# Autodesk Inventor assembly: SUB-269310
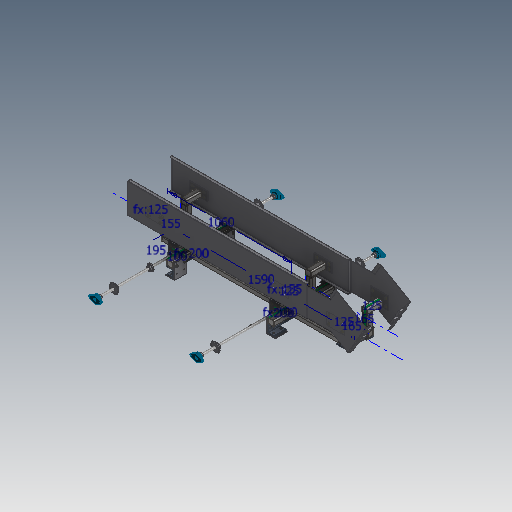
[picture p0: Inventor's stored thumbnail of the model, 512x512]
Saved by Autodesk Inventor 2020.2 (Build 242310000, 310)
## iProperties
Created: 2000-02
Part Number: SUB-269310
Document SubType Name: Assembly
Designer: sspink
Mass: 65770.7 g
Surface Area: 56911.4 cm^2
Volume: 11460 cm^3
Density: 5.73915 g/cm^3
Control State: 0
Checked Out: False
Master: False
Shininess: 0.0
Length Units: 11269
Angle Units: 11279
Time Units: 11290
Mass Units: 11283
Length Display Precision: 3
Angle Display Precision: 2
Compacted: True
Dimensions: 570,1x1560x2033,5 mm
Mass: 65,771 kg
DocNumber: SUB-269310.iam
Folder: 01 - Themengebiete\Simplification\01 - Packaging machine\
VDS_Category: 3D Komponenten
Density: 0.0
Volumn: 0.0
Area: 0.0
PropertySet Name: Model Information
Author: sspink
Revision Number: -
Title: SUB-269310
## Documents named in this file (26)
- D:\07 - DEMODATEN\OTX 2019 - Dataset - UPDATE - Dez2019\Designs\07-Packing machine\SUB-269310.iam
- D:\07 - DEMODATEN\OTX 2019 - Dataset - UPDATE - Dez2019\Designs\07-Packing machine\500666L.iam
- D:\07 - DEMODATEN\OTX 2019 - Dataset - UPDATE - Dez2019\Designs\07-Packing machine\Parts\ADSK-011632.ipt
- D:\07 - DEMODATEN\OTX 2019 - Dataset - UPDATE - Dez2019\Designs\07-Packing machine\Parts\ADSK-011655.ipt
- D:\07 - DEMODATEN\OTX 2019 - Dataset - UPDATE - Dez2019\Designs\07-Packing machine\500665L.iam
- D:\07 - DEMODATEN\OTX 2019 - Dataset - UPDATE - Dez2019\Designs\07-Packing machine\Parts\ADSK-011625.ipt
- D:\07 - DEMODATEN\OTX 2019 - Dataset - UPDATE - Dez2019\Designs\07-Packing machine\Parts\ADSK-011656.ipt
- D:\07 - DEMODATEN\OTX 2019 - Dataset - UPDATE - Dez2019\Designs\07-Packing machine\Parts\ADSK-011657.ipt
- D:\07 - DEMODATEN\OTX 2019 - Dataset - UPDATE - Dez2019\Designs\07-Packing machine\Parts\ADSK-011333.ipt
- D:\07 - DEMODATEN\OTX 2019 - Dataset - UPDATE - Dez2019\Designs\07-Packing machine\Parts\ADSK-011663.ipt
- D:\07 - DEMODATEN\OTX 2019 - Dataset - UPDATE - Dez2019\Designs\07-Packing machine\Parts\ADSK-011714.ipt
- D:\07 - DEMODATEN\OTX 2019 - Dataset - UPDATE - Dez2019\Designs\07-Packing machine\Parts\ADSK-011716.ipt
- D:\07 - DEMODATEN\OTX 2019 - Dataset - UPDATE - Dez2019\Designs\07-Packing machine\Parts\ADSK-011741.ipt
- D:\07 - DEMODATEN\OTX 2019 - Dataset - UPDATE - Dez2019\Designs\07-Packing machine\Parts\ADSK-011723.ipt
- D:\07 - DEMODATEN\OTX 2019 - Dataset - UPDATE - Dez2019\Designs\07-Packing machine\Parts\ADSK-011664.ipt
- D:\07 - DEMODATEN\OTX 2019 - Dataset - UPDATE - Dez2019\Designs\07-Packing machine\500665R.iam
- D:\07 - DEMODATEN\OTX 2019 - Dataset - UPDATE - Dez2019\Designs\07-Packing machine\Parts\ADSK-011626.ipt
- D:\07 - DEMODATEN\OTX 2019 - Dataset - UPDATE - Dez2019\Content Center Files\de-DE\ISO 2491 - A\ISO 2491 - A  5 x 3 x 32.ipt
- D:\07 - DEMODATEN\OTX 2019 - Dataset - UPDATE - Dez2019\Content Center Files\de-DE\ISO 4026\ISO 4026 - M5 x 8 - ISO.ipt
- D:\07 - DEMODATEN\OTX 2019 - Dataset - UPDATE - Dez2019\Content Center Files\de-DE\DIN 125-1  B\DIN 125-1 - B 8,4.ipt
- D:\07 - DEMODATEN\OTX 2019 - Dataset - UPDATE - Dez2019\Content Center Files\de-DE\ISO 4762(2)\ISO 4762 - M8 x 16ISO.ipt
- D:\07 - DEMODATEN\OTX 2019 - Dataset - UPDATE - Dez2019\Content Center Files\de-DE\ISO 4762(2)\ISO 4762 - M8 x 20ISO.ipt
- D:\07 - DEMODATEN\OTX 2019 - Dataset - UPDATE - Dez2019\Content Center Files\de-DE\ISO 10642(1)\ISO 10642 - M8x16.ipt
- D:\07 - DEMODATEN\OTX 2019 - Dataset - UPDATE - Dez2019\Content Center Files\de-DE\DIN 125-1  B\DIN 125-1 - B 5,3.ipt
- D:\07 - DEMODATEN\OTX 2019 - Dataset - UPDATE - Dez2019\Content Center Files\de-DE\ISO 4762(2)\ISO 4762 - M5 x 12ISO.ipt
- D:\07 - DEMODATEN\OTX 2019 - Dataset - UPDATE - Dez2019\Content Center Files\de-DE\ISO 4032(1)\ISO 4032 - M8DIN EN.ipt
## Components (274 placed, 25 different names)
1. 500666L:2 [sub-assembly] — Fluchtend:34, Fluchtend:35, Fluchtend:36, Passend:51, Passend:52, Passend:53, Passend:54, Fluchtend:37, Passend:58, Passend:59, Passend:64, Fluchtend:38, Fluchtend:41, Passend:143, Passend:81, Passend:82, Fluchtend:46, Passend:115, Passend:116, Passend:117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
2. ADSK-011632:3 — Passend:45, Passend:46, Passend:47
3. ADSK-011655:1 — Fluchtend:34, Passend:45, Passend:46, Passend:47, Passend:48, Passend:49, Passend:50, Passend:122, Fluchtend:55, Passend:414, Passend:416
4. ADSK-011655:2 — Fluchtend:35, Fluchtend:36, Passend:56, Passend:57, Passend:60, Passend:61, Passend:62, Passend:63, Passend:121, Passend:426, Passend:428
5. 500665L:1 [sub-assembly] — Passend:112, Passend:113, Passend:114, Passend:229, Passend:230, Fluchtend:77, Passend:257, Passend:259, Passend:326, Passend:328, Passend:330, Passend:332
6. ADSK-011625:1 — Passend:75, Passend:76, Passend:77, Passend:78, Passend:112, Passend:113, Passend:114, Passend:155, Passend:156
7. ADSK-011656:1 — Passend:115, Passend:116, Passend:117
8. ADSK-011657:1 — Passend:82, Passend:83, Fluchtend:47, Passend:84, Passend:85, Passend:90, Passend:92, Passend:98, Fluchtend:62, Fluchtend:66
9. ADSK-011657:2 — Passend:81, Fluchtend:46, Fluchtend:47, Passend:86, Passend:87, Passend:88, Passend:89, Passend:91, Passend:97, Fluchtend:61, Fluchtend:65, Passend:239, Passend:241, Passend:243, Passend:245
10. ADSK-011333:1 — Passend:86, Passend:87, Passend:88, Passend:263, Passend:265
11. ADSK-011333:2 — Passend:83, Passend:84, Passend:85, Passend:275, Passend:277
12. ADSK-011663:1 — Mate:34, Passend:93, Fluchtend:50, Passend:96, Passend:102, Passend:101, Passend:108, Passend:168, Passend:169, Passend:170, Passend:171, Passend:172, Passend:173, Fluchtend:67, Passend:174, Passend:226
13. ADSK-011663:2 — Passend:32, Mate:35, Passend:94, Fluchtend:51, Passend:95, Passend:103, Passend:177, Passend:178, Passend:179, Passend:180
14. ADSK-011714:1 — Passend:90, Passend:92, Passend:94, Fluchtend:51, Passend:100, Passend:167, Passend:182
15. ADSK-011714:2 — Passend:96, Passend:97, Passend:99, Passend:105
16. ADSK-011714:3 — Passend:95, Passend:98, Passend:100, Passend:104
17. ADSK-011714:4 — Passend:89, Passend:91, Passend:93, Fluchtend:50, Passend:99, Passend:106, Fluchtend:52, Passend:181
18. ADSK-011716:1 — Passend:102, Passend:105
19. ADSK-011716:2 — Passend:103, Passend:104
20. ADSK-011716:3 — Passend:32, Passend:167
21. ADSK-011716:4 — Passend:101, Passend:106
22. ADSK-011723:2 — Passend:108, Fluchtend:52, Passend:111, Fluchtend:67, Passend:175
23. ADSK-011741:1 — Mate:35, Fluchtend:53, Passend:180, Drehung:1
24. ADSK-011741:2 — Mate:34, Passend:111, Fluchtend:53, Passend:174, Drehung:1
25. ADSK-011664:1 — Passend:75, Passend:76, Passend:155
26. ADSK-011664:2 — Passend:77, Passend:78, Passend:156
27. ADSK-011632:6 — Passend:48, Passend:49, Passend:50
28. ADSK-011632:7 — Passend:51, Passend:53, Passend:55, Fluchtend:37
29. ADSK-011632:8 — Passend:52, Passend:54, Passend:55
30. ADSK-011632:9 — Passend:59, Passend:64, Fluchtend:38, Fluchtend:39, Passend:65
31. ADSK-011632:10 — Passend:58, Fluchtend:39, Passend:65
32. ADSK-011632:11 — Passend:57, Passend:60, Passend:61
33. ADSK-011632:12 — Passend:56, Passend:62, Passend:63
34. ADSK-011632:13 — Fluchtend:41, Passend:143, Passend:142
35. ADSK-011632:14
36. ADSK-011632:18 — Passend:227, Passend:279, Passend:280
37. ADSK-011632:19 — Passend:228, Passend:278, Fluchtend:80, Passend:280
38. ADSK-011632:20 — Passend:232, Passend:233, Passend:235, Fluchtend:78
39. ADSK-011632:21 — Passend:231, Passend:234, Passend:235
40. ADSK-011632:22 — Passend:236, Fluchtend:79, Passend:237
41. ADSK-011632:15
42. ADSK-011632:16
43. ADSK-011632:17
44. ADSK-011655:3 — Passend:135, Fluchtend:56, Fluchtend:57, Passend:418, Passend:420
45. ADSK-011655:4 — Passend:136, Fluchtend:58, Fluchtend:59, Passend:422, Passend:424
46. ADSK-011656:2 — Passend:137, Passend:147, Passend:148
47. 500665R:1 [sub-assembly] — Passend:140, Fluchtend:60, Passend:141, Passend:144, Passend:145, Passend:146, Passend:255, Passend:261, Passend:318, Passend:320, Passend:322, Passend:324
48. ADSK-011626:1 — Passend:144, Passend:145, Passend:146, Passend:149, Passend:150, Passend:151, Passend:152, Passend:153, Passend:154
49. ADSK-011664:3 — Passend:149, Passend:152, Passend:153
50. ADSK-011664:4 — Passend:150, Passend:151, Passend:154
51. ADSK-011657:3 — Fluchtend:64, Passend:163, Fluchtend:66, Passend:164, Passend:165, Passend:166, Passend:224, Fluchtend:76, Passend:225
52. ADSK-011657:4 — Passend:157, Fluchtend:63, Fluchtend:65, Passend:160, Passend:161, Passend:162, Passend:202, Passend:203, Passend:204, Passend:247, Passend:249, Passend:251, Passend:253
53. ADSK-011333:3 — Passend:164, Passend:165, Passend:166, Passend:271, Passend:273
54. ADSK-011333:4 — Passend:160, Passend:161, Passend:162, Passend:267, Passend:269
55. ADSK-011663:3 — Passend:187, Passend:188, Passend:202, Passend:226
56. ADSK-011714:5 — Passend:204
57. ADSK-011714:6 — Passend:203, Fluchtend:71
58. ADSK-011716:5 — Passend:188
59. ADSK-011716:6 — Passend:187
60. ADSK-011723:3
61. ADSK-011741:3 — Drehung:2
62. ADSK-011663:4 — Passend:209, Passend:210, Passend:224
63. ADSK-011714:7 — Passend:225
64. ADSK-011714:8 — Fluchtend:75, Fluchtend:76
65. ADSK-011716:7 — Passend:210
66. ADSK-011716:8 — Passend:209
67. ADSK-011723:4
68. ADSK-011741:4 — Drehung:2
69. DIN 125-1 B B 8,4:13
70. DIN 125-1 B B 8,4:14 — Passend:398, Passend:400, Passend:402, Passend:404
71. DIN 125-1 B B 8,4:15
72. DIN 125-1 B B 8,4:16
73. DIN 125-1 B B 8,4:17 — Passend:318
74. DIN 125-1 B B 8,4:18 — Passend:320
75. DIN 125-1 B B 8,4:19 — Passend:322
76. DIN 125-1 B B 8,4:20 — Passend:324
77. DIN 125-1 B B 8,4:21 — Passend:326
78. DIN 125-1 B B 8,4:22 — Passend:328
79. DIN 125-1 B B 8,4:23 — Passend:330
80. DIN 125-1 B B 8,4:24 — Passend:332
81. DIN 125-1 B B 8,4:25 — Passend:406, Passend:408, Passend:410, Passend:412
82. DIN 125-1 B B 8,4:26
83. DIN 125-1 B B 8,4:27
84. DIN 125-1 B B 8,4:28
85. DIN EN 24032 M8:1
86. DIN EN 24032 M8:2
87. DIN EN 24032 M8:3
88. DIN EN 24032 M8:4
89. DIN EN 24032 M8:5
90. DIN EN 24032 M8:6
91. DIN EN 24032 M8:7
92. DIN EN 24032 M8:8
93. DIN 125-1 B B 8,4:29 — Passend:334
94. DIN 125-1 B B 8,4:30 — Passend:336
95. DIN 125-1 B B 8,4:31 — Passend:338
96. DIN 125-1 B B 8,4:32 — Passend:340
97. DIN 125-1 B B 8,4:33 — Passend:342
98. DIN 125-1 B B 8,4:34 — Passend:344
99. DIN 125-1 B B 8,4:35 — Passend:346
100. DIN 125-1 B B 8,4:36 — Passend:348
101. DIN 125-1 B B 8,4:37 — Passend:382, Passend:384, Passend:386, Passend:388, Passend:390, Passend:392, Passend:394, Passend:396
102. DIN 125-1 B B 8,4:38
103. DIN 125-1 B B 8,4:39
104. DIN 125-1 B B 8,4:40
105. DIN 125-1 B B 8,4:41
106. DIN 125-1 B B 8,4:42
107. DIN 125-1 B B 8,4:43
108. DIN 125-1 B B 8,4:44
109. DIN 125-1 B B 8,4:45
110. DIN 125-1 B B 8,4:46
111. DIN 125-1 B B 8,4:47
112. DIN 125-1 B B 8,4:48 — Passend:366, Passend:368, Passend:370, Passend:372, Passend:374, Passend:376, Passend:378, Passend:380
113. DIN 125-1 B B 8,4:49
114. DIN 125-1 B B 8,4:50
115. DIN 125-1 B B 8,4:51
116. DIN 125-1 B B 8,4:52
117. DIN 125-1 B B 8,4:53 — Passend:350
118. DIN 125-1 B B 8,4:54 — Passend:352
119. DIN 125-1 B B 8,4:55 — Passend:354
120. DIN 125-1 B B 8,4:56 — Passend:356
121. DIN 125-1 B B 8,4:57 — Passend:358
122. DIN 125-1 B B 8,4:58 — Passend:360
123. DIN 125-1 B B 8,4:59 — Passend:362
124. DIN 125-1 B B 8,4:60 — Passend:364
125. DIN EN 24032 M8:9
126. DIN EN 24032 M8:10
127. DIN EN 24032 M8:11
128. DIN EN 24032 M8:12
129. DIN EN 24032 M8:13
130. DIN EN 24032 M8:14
131. DIN EN 24032 M8:15
132. DIN EN 24032 M8:16
133. DIN EN 24032 M8:17
134. DIN EN 24032 M8:18
135. DIN EN 24032 M8:19
136. DIN EN 24032 M8:20
137. DIN EN 24032 M8:21
138. DIN EN 24032 M8:22
139. DIN EN 24032 M8:23
140. DIN EN 24032 M8:24
141. ISO 4762 M8 x 20:9 — Passend:366
142. ISO 4762 M8 x 20:10 — Passend:368
143. ISO 4762 M8 x 20:11 — Passend:370
144. ISO 4762 M8 x 20:12 — Passend:372
145. ISO 4762 M8 x 20:13 — Passend:374
146. ISO 4762 M8 x 20:14 — Passend:376
147. ISO 4762 M8 x 20:15 — Passend:378
148. ISO 4762 M8 x 20:16 — Passend:380
149. ISO 4762 M8 x 20:17 — Passend:382
150. ISO 4762 M8 x 20:18 — Passend:384
151. ISO 4762 M8 x 20:19 — Passend:386
152. ISO 4762 M8 x 20:20 — Passend:388
153. ISO 4762 M8 x 20:21 — Passend:390
154. ISO 4762 M8 x 20:22 — Passend:392
155. ISO 4762 M8 x 20:23 — Passend:394
156. ISO 4762 M8 x 20:24 — Passend:396
157. ISO 4762 M8 x 20:25 — Passend:398
158. ISO 4762 M8 x 20:26 — Passend:400
159. ISO 4762 M8 x 20:27 — Passend:402
160. ISO 4762 M8 x 20:28 — Passend:404
161. ISO 4762 M8 x 20:29 — Passend:406
162. ISO 4762 M8 x 20:30 — Passend:408
163. ISO 4762 M8 x 20:31 — Passend:410
164. ISO 4762 M8 x 20:32 — Passend:412
165. DIN 125-1 B B 8,4:61 — Passend:414
166. DIN 125-1 B B 8,4:62 — Passend:416, Passend:434, Passend:436
167. DIN 125-1 B B 8,4:63 — Passend:418, Passend:438, Passend:440
168. DIN 125-1 B B 8,4:64 — Passend:420
169. DIN 125-1 B B 8,4:65 — Passend:422, Passend:442, Passend:444
170. DIN 125-1 B B 8,4:66 — Passend:424
171. DIN 125-1 B B 8,4:67 — Passend:426, Passend:430, Passend:432
172. DIN 125-1 B B 8,4:68 — Passend:428
173. ISO 4762 M8 x 16:13 — Passend:430
174. ISO 4762 M8 x 16:14 — Passend:432
175. ISO 4762 M8 x 16:15 — Passend:434
176. ISO 4762 M8 x 16:16 — Passend:436
177. ISO 4762 M8 x 16:17 — Passend:438
178. ISO 4762 M8 x 16:18 — Passend:440
179. ISO 4762 M8 x 16:19 — Passend:442
180. ISO 4762 M8 x 16:20 — Passend:444
181. ISO 10642 M8x16:1
182. ISO 10642 M8x16:2
183. ISO 10642 M8x16:3
184. ISO 10642 M8x16:4
185. ISO 10642 M8x16:5
186. ISO 10642 M8x16:6
187. ISO 10642 M8x16:7
188. ISO 10642 M8x16:8
189. ISO 10642 M8x16:9
190. ISO 10642 M8x16:10
191. ISO 10642 M8x16:11
192. ISO 10642 M8x16:12
193. ISO 10642 M8x16:13
194. ISO 10642 M8x16:14
195. ISO 10642 M8x16:15
196. ISO 10642 M8x16:16
197. ISO 10642 M8x16:17
198. ISO 10642 M8x16:18
199. ISO 10642 M8x16:19
200. ISO 10642 M8x16:20
201. ISO 10642 M8x16:21
202. ISO 10642 M8x16:22
203. ISO 10642 M8x16:23
204. ISO 10642 M8x16:24
205. ISO 10642 M8x16:25
206. ISO 10642 M8x16:26
207. ISO 10642 M8x16:27
208. ISO 10642 M8x16:28
209. ISO 10642 M8x16:29
210. ISO 10642 M8x16:30
211. ISO 10642 M8x16:31
212. ISO 10642 M8x16:32
213. ISO 10642 M8x16:33
214. ISO 10642 M8x16:34
215. ISO 10642 M8x16:35
216. ISO 10642 M8x16:36
217. DIN 125-1 B B 5,3:1
218. DIN 125-1 B B 5,3:2
219. DIN 125-1 B B 5,3:3
220. DIN 125-1 B B 5,3:4
221. DIN 125-1 B B 5,3:5
222. DIN 125-1 B B 5,3:6
223. DIN 125-1 B B 5,3:7
224. DIN 125-1 B B 5,3:8
225. ISO 4762 M5 x 12:1
226. ISO 4762 M5 x 12:2
227. ISO 4762 M5 x 12:3
228. ISO 4762 M5 x 12:4
229. ISO 4762 M5 x 12:5
230. ISO 4762 M5 x 12:6
231. ISO 4762 M5 x 12:7
232. ISO 4762 M5 x 12:8
233. DIN 125-1 B B 8,4:1 — Passend:239
234. DIN 125-1 B B 8,4:2 — Passend:241
235. DIN 125-1 B B 8,4:3 — Passend:243
236. DIN 125-1 B B 8,4:4 — Passend:245
237. DIN 125-1 B B 8,4:5 — Passend:247
238. DIN 125-1 B B 8,4:6 — Passend:249
239. DIN 125-1 B B 8,4:7 — Passend:251
240. DIN 125-1 B B 8,4:8 — Passend:253
241. DIN 125-1 B B 8,4:9 — Passend:255
242. DIN 125-1 B B 8,4:10 — Passend:257
243. DIN 125-1 B B 8,4:11 — Passend:259
244. DIN 125-1 B B 8,4:12 — Passend:261
245. ISO 4762 M8 x 16:1
246. ISO 4762 M8 x 16:2
247. ISO 4762 M8 x 16:3
248. ISO 4762 M8 x 16:4
249. ISO 4762 M8 x 20:1
250. ISO 4762 M8 x 20:2
251. ISO 4762 M8 x 20:3
252. ISO 4762 M8 x 20:4
253. ISO 4762 M8 x 20:5
254. ISO 4762 M8 x 20:6
255. ISO 4762 M8 x 20:7
256. ISO 4762 M8 x 20:8
257. ISO 4762 M8 x 16:5 — Passend:263
258. ISO 4762 M8 x 16:6 — Passend:265
259. ISO 4762 M8 x 16:7 — Passend:267
260. ISO 4762 M8 x 16:8 — Passend:269
261. ISO 4762 M8 x 16:9 — Passend:271
262. ISO 4762 M8 x 16:10 — Passend:273
263. ISO 4762 M8 x 16:11 — Passend:275
264. ISO 4762 M8 x 16:12 — Passend:277
265. ISO 2491 A A  5 x 3 x 32:6
266. ISO 2491 A A  5 x 3 x 32:7
267. ISO 4026 M5 x 8:3
268. ISO 2491 A A  5 x 3 x 32:4
269. ISO 2491 A A  5 x 3 x 32:5
270. ISO 4026 M5 x 8:2
271. ISO 2491 A A  5 x 3 x 32:1 — Passend:168, Passend:172, Passend:173, Passend:176
272. ISO 2491 A A  5 x 3 x 32:2 — Passend:169, Passend:170, Passend:171
273. ISO 4026 M5 x 8:1 — Passend:175, Passend:176
274. ISO 2491 A A  5 x 3 x 32:3 — Passend:177, Passend:178, Passend:179
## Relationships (251: Mate 216, Flush 33, RelateRotation 2)
- Passend:32 [Mate]: ADSK-011663:2 ↔ ADSK-011716:3
- Mate:34: ADSK-011663:1 ↔ ADSK-011741:2
- Mate:35: ADSK-011663:2 ↔ ADSK-011741:1
- Fluchtend:34 [Flush]: 500666L:2 ↔ ADSK-011655:1
- Fluchtend:35 [Flush]: 500666L:2 ↔ ADSK-011655:2
- Fluchtend:36 [Flush]: 500666L:2 ↔ ADSK-011655:2
- Passend:45 [Mate]: ADSK-011632:3 ↔ ADSK-011655:1
- Passend:46 [Mate]: ADSK-011632:3 ↔ ADSK-011655:1
- Passend:47 [Mate]: ADSK-011632:3 ↔ ADSK-011655:1
- Passend:48 [Mate]: ADSK-011655:1 ↔ ADSK-011632:6
- Passend:49 [Mate]: ADSK-011655:1 ↔ ADSK-011632:6
- Passend:50 [Mate]: ADSK-011655:1 ↔ ADSK-011632:6
- Passend:51 [Mate]: 500666L:2 ↔ ADSK-011632:7
- Passend:52 [Mate]: 500666L:2 ↔ ADSK-011632:8
- Passend:53 [Mate]: 500666L:2 ↔ ADSK-011632:7
- Passend:54 [Mate]: 500666L:2 ↔ ADSK-011632:8
- Passend:55 [Mate]: ADSK-011632:7 ↔ ADSK-011632:8
- Fluchtend:37 [Flush]: 500666L:2 ↔ ADSK-011632:7
- Passend:56 [Mate]: ADSK-011655:2 ↔ ADSK-011632:12
- Passend:57 [Mate]: ADSK-011655:2 ↔ ADSK-011632:11
- Passend:58 [Mate]: 500666L:2 ↔ ADSK-011632:10
- Passend:59 [Mate]: 500666L:2 ↔ ADSK-011632:9
- Passend:60 [Mate]: ADSK-011655:2 ↔ ADSK-011632:11
- Passend:61 [Mate]: ADSK-011655:2 ↔ ADSK-011632:11
- Passend:62 [Mate]: ADSK-011655:2 ↔ ADSK-011632:12
- Passend:63 [Mate]: ADSK-011655:2 ↔ ADSK-011632:12
- Passend:64 [Mate]: 500666L:2 ↔ ADSK-011632:9
- Fluchtend:38 [Flush]: 500666L:2 ↔ ADSK-011632:9
- Fluchtend:39 [Flush]: ADSK-011632:9 ↔ ADSK-011632:10
- Passend:65 [Mate]: ADSK-011632:9 ↔ ADSK-011632:10
- Passend:75 [Mate]: ADSK-011625:1 ↔ ADSK-011664:1
- Passend:76 [Mate]: ADSK-011625:1 ↔ ADSK-011664:1
- Passend:77 [Mate]: ADSK-011625:1 ↔ ADSK-011664:2
- Passend:78 [Mate]: ADSK-011625:1 ↔ ADSK-011664:2
- Fluchtend:41 [Flush]: 500666L:2 ↔ ADSK-011632:13
- Passend:143 [Mate]: 500666L:2 ↔ ADSK-011632:13
- Passend:81 [Mate]: 500666L:2 ↔ ADSK-011657:2
- Passend:82 [Mate]: 500666L:2 ↔ ADSK-011657:1
- Passend:83 [Mate]: ADSK-011657:1 ↔ ADSK-011333:2
- Fluchtend:46 [Flush]: 500666L:2 ↔ ADSK-011657:2
- Fluchtend:47 [Flush]: ADSK-011657:1 ↔ ADSK-011657:2
- Passend:84 [Mate]: ADSK-011657:1 ↔ ADSK-011333:2
- Passend:85 [Mate]: ADSK-011657:1 ↔ ADSK-011333:2
- Passend:86 [Mate]: ADSK-011657:2 ↔ ADSK-011333:1
- Passend:87 [Mate]: ADSK-011657:2 ↔ ADSK-011333:1
- Passend:88 [Mate]: ADSK-011657:2 ↔ ADSK-011333:1
- Passend:89 [Mate]: ADSK-011657:2 ↔ ADSK-011714:4
- Passend:90 [Mate]: ADSK-011657:1 ↔ ADSK-011714:1
- Passend:91 [Mate]: ADSK-011657:2 ↔ ADSK-011714:4
- Passend:92 [Mate]: ADSK-011657:1 ↔ ADSK-011714:1
- Passend:93 [Mate]: ADSK-011663:1 ↔ ADSK-011714:4
- Fluchtend:50 [Flush]: ADSK-011663:1 ↔ ADSK-011714:4
- Passend:94 [Mate]: ADSK-011663:2 ↔ ADSK-011714:1
- Fluchtend:51 [Flush]: ADSK-011663:2 ↔ ADSK-011714:1
- Passend:95 [Mate]: ADSK-011663:2 ↔ ADSK-011714:3
- Passend:96 [Mate]: ADSK-011663:1 ↔ ADSK-011714:2
- Passend:97 [Mate]: ADSK-011657:2 ↔ ADSK-011714:2
- Passend:98 [Mate]: ADSK-011657:1 ↔ ADSK-011714:3
- Passend:99 [Mate]: ADSK-011714:2 ↔ ADSK-011714:4
- Passend:100 [Mate]: ADSK-011714:1 ↔ ADSK-011714:3
- Passend:101 [Mate]: ADSK-011663:1 ↔ ADSK-011716:4
- Passend:102 [Mate]: ADSK-011663:1 ↔ ADSK-011716:1
- Passend:103 [Mate]: ADSK-011663:2 ↔ ADSK-011716:2
- Passend:104 [Mate]: ADSK-011714:3 ↔ ADSK-011716:2
- Passend:105 [Mate]: ADSK-011714:2 ↔ ADSK-011716:1
- Passend:106 [Mate]: ADSK-011714:4 ↔ ADSK-011716:4
- Passend:108 [Mate]: ADSK-011663:1 ↔ ADSK-011723:2
- Fluchtend:52 [Flush]: ADSK-011714:4 ↔ ADSK-011723:2
- Passend:111 [Mate]: ADSK-011723:2 ↔ ADSK-011741:2
- Fluchtend:53 [Flush]: ADSK-011741:1 ↔ ADSK-011741:2
- Passend:112 [Mate]: 500665L:1 ↔ ADSK-011625:1
- Passend:113 [Mate]: 500665L:1 ↔ ADSK-011625:1
- Passend:114 [Mate]: 500665L:1 ↔ ADSK-011625:1
- Passend:115 [Mate]: 500666L:2 ↔ ADSK-011656:1
- Passend:116 [Mate]: 500666L:2 ↔ ADSK-011656:1
- Passend:117 [Mate]: 500666L:2 ↔ ADSK-011656:1
- Passend:121 [Mate]: 500666L:2 ↔ ADSK-011655:2
- Passend:122 [Mate]: 500666L:2 ↔ ADSK-011655:1
- Fluchtend:55 [Flush]: 500666L:2 ↔ ADSK-011655:1
- Passend:135 [Mate]: 500666L:2 ↔ ADSK-011655:3
- Fluchtend:56 [Flush]: 500666L:2 ↔ ADSK-011655:3
- Fluchtend:57 [Flush]: 500666L:2 ↔ ADSK-011655:3
- Passend:136 [Mate]: 500666L:2 ↔ ADSK-011655:4
- Fluchtend:58 [Flush]: 500666L:2 ↔ ADSK-011655:4
- Fluchtend:59 [Flush]: 500666L:2 ↔ ADSK-011655:4
- Passend:137 [Mate]: 500666L:2 ↔ ADSK-011656:2
- Passend:140 [Mate]: 500666L:2 ↔ 500665R:1
- Fluchtend:60 [Flush]: 500666L:2 ↔ 500665R:1
- Passend:141 [Mate]: 500666L:2 ↔ 500665R:1
- Passend:142 [Mate]: 500666L:2 ↔ ADSK-011632:13
- Passend:144 [Mate]: 500665R:1 ↔ ADSK-011626:1
- Passend:145 [Mate]: 500665R:1 ↔ ADSK-011626:1
- Passend:146 [Mate]: 500665R:1 ↔ ADSK-011626:1
- Passend:147 [Mate]: 500666L:2 ↔ ADSK-011656:2
- Passend:148 [Mate]: 500666L:2 ↔ ADSK-011656:2
- Passend:149 [Mate]: ADSK-011626:1 ↔ ADSK-011664:3
- Passend:150 [Mate]: ADSK-011626:1 ↔ ADSK-011664:4
- Passend:151 [Mate]: ADSK-011626:1 ↔ ADSK-011664:4
- Passend:152 [Mate]: ADSK-011626:1 ↔ ADSK-011664:3
- Passend:153 [Mate]: ADSK-011626:1 ↔ ADSK-011664:3
- Passend:154 [Mate]: ADSK-011626:1 ↔ ADSK-011664:4
- Passend:155 [Mate]: ADSK-011625:1 ↔ ADSK-011664:1
- Passend:156 [Mate]: ADSK-011625:1 ↔ ADSK-011664:2
- Fluchtend:61 [Flush]: 500666L:2 ↔ ADSK-011657:2
- Fluchtend:62 [Flush]: 500666L:2 ↔ ADSK-011657:1
- Passend:157 [Mate]: 500666L:2 ↔ ADSK-011657:4
- Fluchtend:63 [Flush]: 500666L:2 ↔ ADSK-011657:4
- Fluchtend:64 [Flush]: 500666L:2 ↔ ADSK-011657:3
- Fluchtend:65 [Flush]: ADSK-011657:2 ↔ ADSK-011657:4
- Passend:160 [Mate]: ADSK-011657:4 ↔ ADSK-011333:4
- Passend:161 [Mate]: ADSK-011657:4 ↔ ADSK-011333:4
- Passend:162 [Mate]: ADSK-011657:4 ↔ ADSK-011333:4
- Passend:163 [Mate]: 500666L:2 ↔ ADSK-011657:3
- Fluchtend:66 [Flush]: ADSK-011657:1 ↔ ADSK-011657:3
- Passend:164 [Mate]: ADSK-011657:3 ↔ ADSK-011333:3
- Passend:165 [Mate]: ADSK-011657:3 ↔ ADSK-011333:3
- Passend:166 [Mate]: ADSK-011657:3 ↔ ADSK-011333:3
- Passend:167 [Mate]: ADSK-011714:1 ↔ ADSK-011716:3
- Passend:168 [Mate]: ADSK-011663:1 ↔ ISO 2491 A A  5 x 3 x 32:1
- Passend:169 [Mate]: ADSK-011663:1 ↔ ISO 2491 A A  5 x 3 x 32:2
- Passend:170 [Mate]: ADSK-011663:1 ↔ ISO 2491 A A  5 x 3 x 32:2
- Passend:171 [Mate]: ADSK-011663:1 ↔ ISO 2491 A A  5 x 3 x 32:2
- Passend:172 [Mate]: ADSK-011663:1 ↔ ISO 2491 A A  5 x 3 x 32:1
- Passend:173 [Mate]: ADSK-011663:1 ↔ ISO 2491 A A  5 x 3 x 32:1
- Fluchtend:67 [Flush]: ADSK-011663:1 ↔ ADSK-011723:2
- Passend:174 [Mate]: ADSK-011663:1 ↔ ADSK-011741:2
- Passend:175 [Mate]: ADSK-011723:2 ↔ ISO 4026 M5 x 8:1
- Passend:176 [Mate]: ISO 2491 A A  5 x 3 x 32:1 ↔ ISO 4026 M5 x 8:1
- Passend:177 [Mate]: ADSK-011663:2 ↔ ISO 2491 A A  5 x 3 x 32:3
- Passend:178 [Mate]: ADSK-011663:2 ↔ ISO 2491 A A  5 x 3 x 32:3
- Passend:179 [Mate]: ADSK-011663:2 ↔ ISO 2491 A A  5 x 3 x 32:3
- Passend:180 [Mate]: ADSK-011663:2 ↔ ADSK-011741:1
- Passend:181 [Mate]: ADSK-011714:4
- Passend:182 [Mate]: ADSK-011714:1
- Drehung:1 [RelateRotation]: ADSK-011741:1 ↔ ADSK-011741:2
- Passend:187 [Mate]: ADSK-011663:3 ↔ ADSK-011716:6
- Passend:188 [Mate]: ADSK-011663:3 ↔ ADSK-011716:5
- Passend:202 [Mate]: ADSK-011657:4 ↔ ADSK-011663:3
- Passend:203 [Mate]: ADSK-011657:4 ↔ ADSK-011714:6
- Fluchtend:71 [Flush]: ADSK-011714:6
- Passend:204 [Mate]: ADSK-011657:4 ↔ ADSK-011714:5
- Passend:209 [Mate]: ADSK-011663:4 ↔ ADSK-011716:8
- Passend:210 [Mate]: ADSK-011663:4 ↔ ADSK-011716:7
- Passend:224 [Mate]: ADSK-011657:3 ↔ ADSK-011663:4
- Fluchtend:75 [Flush]: ADSK-011714:8
- Fluchtend:76 [Flush]: ADSK-011657:3 ↔ ADSK-011714:8
- Passend:225 [Mate]: ADSK-011657:3 ↔ ADSK-011714:7
- Drehung:2 [RelateRotation]: ADSK-011741:3 ↔ ADSK-011741:4
- Passend:226 [Mate]: ADSK-011663:1 ↔ ADSK-011663:3
- Passend:227 [Mate]: 500666L:2 ↔ ADSK-011632:18
- Passend:228 [Mate]: 500666L:2 ↔ ADSK-011632:19
- Passend:229 [Mate]: 500666L:2 ↔ 500665L:1
- Passend:230 [Mate]: 500666L:2 ↔ 500665L:1
- Fluchtend:77 [Flush]: 500666L:2 ↔ 500665L:1
- Passend:231 [Mate]: 500666L:2 ↔ ADSK-011632:21
- Passend:232 [Mate]: 500666L:2 ↔ ADSK-011632:20
- Passend:233 [Mate]: 500666L:2 ↔ ADSK-011632:20
- Passend:234 [Mate]: 500666L:2 ↔ ADSK-011632:21
- Passend:235 [Mate]: ADSK-011632:20 ↔ ADSK-011632:21
- Fluchtend:78 [Flush]: 500666L:2 ↔ ADSK-011632:20
- Passend:236 [Mate]: 500666L:2 ↔ ADSK-011632:22
- Fluchtend:79 [Flush]: 500666L:2 ↔ ADSK-011632:22
- Passend:237 [Mate]: 500666L:2 ↔ ADSK-011632:22
- Passend:239 [Mate]: ADSK-011657:2 ↔ DIN 125-1 B B 8,4:1
- Passend:241 [Mate]: ADSK-011657:2 ↔ DIN 125-1 B B 8,4:2
- Passend:243 [Mate]: ADSK-011657:2 ↔ DIN 125-1 B B 8,4:3
- Passend:245 [Mate]: ADSK-011657:2 ↔ DIN 125-1 B B 8,4:4
- Passend:247 [Mate]: ADSK-011657:4 ↔ DIN 125-1 B B 8,4:5
- Passend:249 [Mate]: ADSK-011657:4 ↔ DIN 125-1 B B 8,4:6
- Passend:251 [Mate]: ADSK-011657:4 ↔ DIN 125-1 B B 8,4:7
- Passend:253 [Mate]: ADSK-011657:4 ↔ DIN 125-1 B B 8,4:8
- Passend:255 [Mate]: 500665R:1 ↔ DIN 125-1 B B 8,4:9
- Passend:257 [Mate]: 500665L:1 ↔ DIN 125-1 B B 8,4:10
- Passend:259 [Mate]: 500665L:1 ↔ DIN 125-1 B B 8,4:11
- Passend:261 [Mate]: 500665R:1 ↔ DIN 125-1 B B 8,4:12
- Passend:263 [Mate]: ADSK-011333:1 ↔ ISO 4762 M8 x 16:5
- Passend:265 [Mate]: ADSK-011333:1 ↔ ISO 4762 M8 x 16:6
- Passend:267 [Mate]: ADSK-011333:4 ↔ ISO 4762 M8 x 16:7
- Passend:269 [Mate]: ADSK-011333:4 ↔ ISO 4762 M8 x 16:8
- Passend:271 [Mate]: ADSK-011333:3 ↔ ISO 4762 M8 x 16:9
- Passend:273 [Mate]: ADSK-011333:3 ↔ ISO 4762 M8 x 16:10
- Passend:275 [Mate]: ADSK-011333:2 ↔ ISO 4762 M8 x 16:11
- Passend:277 [Mate]: ADSK-011333:2 ↔ ISO 4762 M8 x 16:12
- Passend:278 [Mate]: 500666L:2 ↔ ADSK-011632:19
- Passend:279 [Mate]: 500666L:2 ↔ ADSK-011632:18
- Fluchtend:80 [Flush]: 500666L:2 ↔ ADSK-011632:19
- Passend:280 [Mate]: ADSK-011632:18 ↔ ADSK-011632:19
- Passend:318 [Mate]: 500665R:1 ↔ DIN 125-1 B B 8,4:17
- Passend:320 [Mate]: 500665R:1 ↔ DIN 125-1 B B 8,4:18
- Passend:322 [Mate]: 500665R:1 ↔ DIN 125-1 B B 8,4:19
- Passend:324 [Mate]: 500665R:1 ↔ DIN 125-1 B B 8,4:20
- Passend:326 [Mate]: 500665L:1 ↔ DIN 125-1 B B 8,4:21
- Passend:328 [Mate]: 500665L:1 ↔ DIN 125-1 B B 8,4:22
- Passend:330 [Mate]: 500665L:1 ↔ DIN 125-1 B B 8,4:23
- Passend:332 [Mate]: 500665L:1 ↔ DIN 125-1 B B 8,4:24
- Passend:334 [Mate]: 500666L:2 ↔ DIN 125-1 B B 8,4:29
- Passend:336 [Mate]: 500666L:2 ↔ DIN 125-1 B B 8,4:30
- Passend:338 [Mate]: 500666L:2 ↔ DIN 125-1 B B 8,4:31
- Passend:340 [Mate]: 500666L:2 ↔ DIN 125-1 B B 8,4:32
- Passend:342 [Mate]: 500666L:2 ↔ DIN 125-1 B B 8,4:33
- Passend:344 [Mate]: 500666L:2 ↔ DIN 125-1 B B 8,4:34
- Passend:346 [Mate]: 500666L:2 ↔ DIN 125-1 B B 8,4:35
- Passend:348 [Mate]: 500666L:2 ↔ DIN 125-1 B B 8,4:36
- Passend:350 [Mate]: 500666L:2 ↔ DIN 125-1 B B 8,4:53
- Passend:352 [Mate]: 500666L:2 ↔ DIN 125-1 B B 8,4:54
- Passend:354 [Mate]: 500666L:2 ↔ DIN 125-1 B B 8,4:55
- Passend:356 [Mate]: 500666L:2 ↔ DIN 125-1 B B 8,4:56
- Passend:358 [Mate]: 500666L:2 ↔ DIN 125-1 B B 8,4:57
- Passend:360 [Mate]: 500666L:2 ↔ DIN 125-1 B B 8,4:58
- Passend:362 [Mate]: 500666L:2 ↔ DIN 125-1 B B 8,4:59
- Passend:364 [Mate]: 500666L:2 ↔ DIN 125-1 B B 8,4:60
- Passend:366 [Mate]: DIN 125-1 B B 8,4:48 ↔ ISO 4762 M8 x 20:9
- Passend:368 [Mate]: DIN 125-1 B B 8,4:48 ↔ ISO 4762 M8 x 20:10
- Passend:370 [Mate]: DIN 125-1 B B 8,4:48 ↔ ISO 4762 M8 x 20:11
- Passend:372 [Mate]: DIN 125-1 B B 8,4:48 ↔ ISO 4762 M8 x 20:12
- Passend:374 [Mate]: DIN 125-1 B B 8,4:48 ↔ ISO 4762 M8 x 20:13
- Passend:376 [Mate]: DIN 125-1 B B 8,4:48 ↔ ISO 4762 M8 x 20:14
- Passend:378 [Mate]: DIN 125-1 B B 8,4:48 ↔ ISO 4762 M8 x 20:15
- Passend:380 [Mate]: DIN 125-1 B B 8,4:48 ↔ ISO 4762 M8 x 20:16
- Passend:382 [Mate]: DIN 125-1 B B 8,4:37 ↔ ISO 4762 M8 x 20:17
- Passend:384 [Mate]: DIN 125-1 B B 8,4:37 ↔ ISO 4762 M8 x 20:18
- Passend:386 [Mate]: DIN 125-1 B B 8,4:37 ↔ ISO 4762 M8 x 20:19
- Passend:388 [Mate]: DIN 125-1 B B 8,4:37 ↔ ISO 4762 M8 x 20:20
- Passend:390 [Mate]: DIN 125-1 B B 8,4:37 ↔ ISO 4762 M8 x 20:21
- Passend:392 [Mate]: DIN 125-1 B B 8,4:37 ↔ ISO 4762 M8 x 20:22
- Passend:394 [Mate]: DIN 125-1 B B 8,4:37 ↔ ISO 4762 M8 x 20:23
- Passend:396 [Mate]: DIN 125-1 B B 8,4:37 ↔ ISO 4762 M8 x 20:24
- Passend:398 [Mate]: DIN 125-1 B B 8,4:14 ↔ ISO 4762 M8 x 20:25
- Passend:400 [Mate]: DIN 125-1 B B 8,4:14 ↔ ISO 4762 M8 x 20:26
- Passend:402 [Mate]: DIN 125-1 B B 8,4:14 ↔ ISO 4762 M8 x 20:27
- Passend:404 [Mate]: DIN 125-1 B B 8,4:14 ↔ ISO 4762 M8 x 20:28
- Passend:406 [Mate]: DIN 125-1 B B 8,4:25 ↔ ISO 4762 M8 x 20:29
- Passend:408 [Mate]: DIN 125-1 B B 8,4:25 ↔ ISO 4762 M8 x 20:30
- Passend:410 [Mate]: DIN 125-1 B B 8,4:25 ↔ ISO 4762 M8 x 20:31
- Passend:412 [Mate]: DIN 125-1 B B 8,4:25 ↔ ISO 4762 M8 x 20:32
- Passend:414 [Mate]: ADSK-011655:1 ↔ DIN 125-1 B B 8,4:61
- Passend:416 [Mate]: ADSK-011655:1 ↔ DIN 125-1 B B 8,4:62
- Passend:418 [Mate]: ADSK-011655:3 ↔ DIN 125-1 B B 8,4:63
- Passend:420 [Mate]: ADSK-011655:3 ↔ DIN 125-1 B B 8,4:64
- Passend:422 [Mate]: ADSK-011655:4 ↔ DIN 125-1 B B 8,4:65
- Passend:424 [Mate]: ADSK-011655:4 ↔ DIN 125-1 B B 8,4:66
- Passend:426 [Mate]: ADSK-011655:2 ↔ DIN 125-1 B B 8,4:67
- Passend:428 [Mate]: ADSK-011655:2 ↔ DIN 125-1 B B 8,4:68
- Passend:430 [Mate]: DIN 125-1 B B 8,4:67 ↔ ISO 4762 M8 x 16:13
- Passend:432 [Mate]: DIN 125-1 B B 8,4:67 ↔ ISO 4762 M8 x 16:14
- Passend:434 [Mate]: DIN 125-1 B B 8,4:62 ↔ ISO 4762 M8 x 16:15
- Passend:436 [Mate]: DIN 125-1 B B 8,4:62 ↔ ISO 4762 M8 x 16:16
- Passend:438 [Mate]: DIN 125-1 B B 8,4:63 ↔ ISO 4762 M8 x 16:17
- Passend:440 [Mate]: DIN 125-1 B B 8,4:63 ↔ ISO 4762 M8 x 16:18
- Passend:442 [Mate]: DIN 125-1 B B 8,4:65 ↔ ISO 4762 M8 x 16:19
- Passend:444 [Mate]: DIN 125-1 B B 8,4:65 ↔ ISO 4762 M8 x 16:20
## Named parameters: d311_d208 = 0, d312_d209 = 0, d313_d210 = 0, d314_d211 = 0, d315_d212 = 0, d316_d213 = 0, d317_d208 = 0, d318_d209 = 0, d319_d210 = 0, d320_d211 = 0, d321_d212 = 0, d322_d213 = 0, d390_d373 = 0, d391_d374 = 0, d392_d375 = 0, d393_d376 = 0, d394_d377 = 0, d395_d378 = 0, d396_d379 = 0, d397_d380 = 0, d398_d381 = 0, d399_d382 = 0, d400_d274 = 0, d402_d279 = 0, d403_d282 = -755 mm, d404_d284 = 0, d405_d285 = 0, d406_d288 = 0, d407_d289 = 0, d408_d292 = 0, d409_d293 = 278.75 mm, d410_d294 = -312 mm, d411_d159 = 0, d416_d373 = 0, d417_d374 = 0, d418_d375 = 0, d419_d376 = 0, d420_d377 = 0, d421_d378 = 0, d422_d379 = 0, d423_d380 = 0, d424_d381 = 0, d425_d382 = 0, d426_d274 = 0, d428_d279 = 0, d429_d282 = -755 mm, d430_d284 = 0, d431_d285 = 0, d432_d288 = 0, d433_d289 = 0, d434_d292 = 0, d435_d293 = 278.75 mm, d436_d294 = -312 mm, d437_d159 = 0
